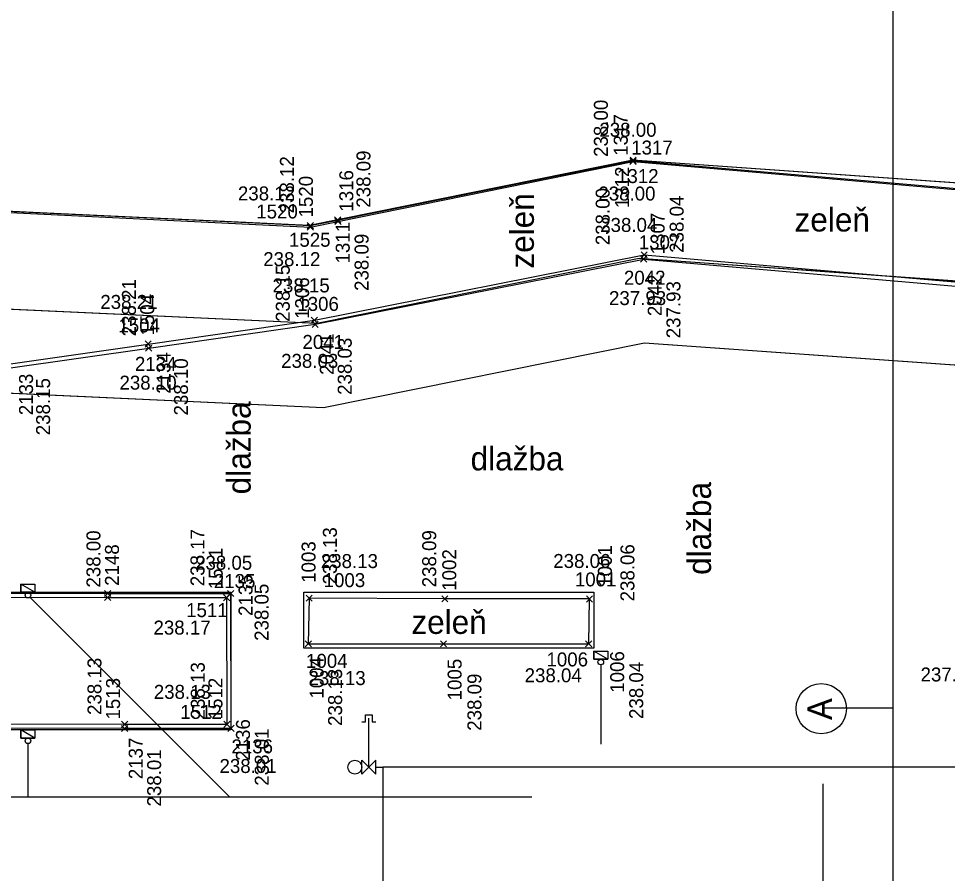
# Model space of a CAD drawing. Extents: x -264205 to -263659, y -1242401 to -1241986.
# Drawn here: x -263937.18 to -263903.94, y -1242086.44 to -1242055.86 of the extents above; entities that cross this region are included whole.
import ezdxf

# ---------------------------------------------------------------- set-up
doc = ezdxf.new("R2010")
doc.units = 0
for name, color, linetype in [('BOD_CISLO_2-2', 7, 'Continuous'), ('BOD_CISLO_2-3', 7, 'Continuous'), ('BOD_SYMBOL_2-2', 7, 'Continuous'), ('BOD_SYMBOL_2-3', 7, 'Continuous'), ('BOD_VYSKA_2-2', 7, 'Continuous'), ('BOD_VYSKA_2-3', 7, 'Continuous'), ('HESCON_OSI_STAVBY_KFA', 7, 'Continuous'), ('POPIS_2-2', 7, 'Continuous'), ('POPIS_2-3', 7, 'Continuous'), ('PROJEKT_OBRUBNIKY_KOMUNIKACIE', 7, 'Continuous'), ('RAM_NA_TLAC_2-3_1-250', 7, 'Continuous'), ('SITUACIA_DSP_2D', 7, 'Continuous'), ('SO_20-4_OBRUBNIKY_DOLNA_HRANA', 7, 'Continuous'), ('SO_20-4_OBRUBNIKY_HORNA_HRANA', 7, 'Continuous')]:
    doc.layers.add(name, color=color, linetype=linetype)

msp = doc.modelspace()

# ---------------------------------------------------------------- linework, layer by layer
at = {"layer": 'BOD_SYMBOL_2-2'}
for p, q in [((-263915.299, -1242061.082), (-263915.078, -1242060.86)), ((-263915.078, -1242061.082), (-263915.299, -1242060.86)), ((-263915.291, -1242061.039), (-263915.071, -1242060.818)), ((-263915.071, -1242061.039), (-263915.291, -1242060.818)), ((-263926.851, -1242063.374), (-263926.629, -1242063.154)), ((-263926.629, -1242063.374), (-263926.851, -1242063.154)), ((-263926.846, -1242063.43), (-263926.626, -1242063.208)), ((-263926.626, -1242063.43), (-263926.846, -1242063.208)), ((-263925.87, -1242063.177), (-263925.649, -1242062.955)), ((-263925.649, -1242063.177), (-263925.87, -1242062.955)), ((-263925.861, -1242063.222), (-263925.639, -1242063.002)), ((-263925.639, -1242063.222), (-263925.861, -1242063.002)), ((-263914.9, -1242064.418), (-263914.68, -1242064.198)), ((-263914.68, -1242064.418), (-263914.9, -1242064.198)), ((-263914.916, -1242064.569), (-263914.696, -1242064.349)), ((-263914.696, -1242064.569), (-263914.916, -1242064.349)), ((-263926.704, -1242066.758), (-263926.482, -1242066.536)), ((-263926.482, -1242066.758), (-263926.704, -1242066.536)), ((-263926.674, -1242066.904), (-263926.453, -1242066.683)), ((-263926.453, -1242066.904), (-263926.674, -1242066.683)), ((-263932.65, -1242067.613), (-263932.43, -1242067.391)), ((-263932.43, -1242067.613), (-263932.65, -1242067.391)), ((-263932.632, -1242067.759), (-263932.41, -1242067.539)), ((-263932.41, -1242067.759), (-263932.632, -1242067.539)), ((-263934.1, -1242076.534), (-263933.878, -1242076.312)), ((-263933.878, -1242076.534), (-263934.1, -1242076.312)), ((-263934.099, -1242076.681), (-263933.878, -1242076.461)), ((-263933.878, -1242076.681), (-263934.099, -1242076.461)), ((-263929.843, -1242076.684), (-263929.622, -1242076.463)), ((-263929.622, -1242076.684), (-263929.843, -1242076.463)), ((-263929.699, -1242076.538), (-263929.479, -1242076.316)), ((-263929.479, -1242076.538), (-263929.699, -1242076.316)), ((-263926.891, -1242076.701), (-263926.67, -1242076.481)), ((-263926.67, -1242076.701), (-263926.891, -1242076.481)), ((-263922.035, -1242076.725), (-263921.813, -1242076.505)), ((-263921.813, -1242076.725), (-263922.035, -1242076.505)), ((-263916.854, -1242076.731), (-263916.633, -1242076.511)), ((-263916.633, -1242076.731), (-263916.854, -1242076.511)), ((-263926.92, -1242078.335), (-263926.698, -1242078.113)), ((-263926.698, -1242078.335), (-263926.92, -1242078.113)), ((-263922.082, -1242078.333), (-263921.861, -1242078.113)), ((-263921.861, -1242078.333), (-263922.082, -1242078.113)), ((-263916.887, -1242078.338), (-263916.666, -1242078.117)), ((-263916.666, -1242078.338), (-263916.887, -1242078.117)), ((-263933.492, -1242081.218), (-263933.272, -1242080.997)), ((-263933.272, -1242081.218), (-263933.492, -1242080.997)), ((-263933.49, -1242081.366), (-263933.269, -1242081.144)), ((-263933.269, -1242081.366), (-263933.49, -1242081.144)), ((-263929.833, -1242081.218), (-263929.611, -1242080.998)), ((-263929.611, -1242081.218), (-263929.833, -1242080.998)), ((-263929.688, -1242081.363), (-263929.468, -1242081.141)), ((-263929.468, -1242081.363), (-263929.688, -1242081.141))]:
    msp.add_line(p, q, dxfattribs=at)
at = {"layer": 'BOD_SYMBOL_2-3'}
for p, q in [((-263915.078, -1242061.082), (-263915.299, -1242060.86)), ((-263915.078, -1242060.86), (-263915.299, -1242061.082)), ((-263915.071, -1242061.039), (-263915.291, -1242060.818)), ((-263915.071, -1242060.818), (-263915.291, -1242061.039)), ((-263926.629, -1242063.374), (-263926.851, -1242063.154)), ((-263926.629, -1242063.154), (-263926.851, -1242063.374)), ((-263926.626, -1242063.43), (-263926.846, -1242063.208)), ((-263926.626, -1242063.208), (-263926.846, -1242063.43)), ((-263925.649, -1242063.177), (-263925.87, -1242062.955)), ((-263925.649, -1242062.955), (-263925.87, -1242063.177)), ((-263925.639, -1242063.222), (-263925.861, -1242063.002)), ((-263925.639, -1242063.002), (-263925.861, -1242063.222)), ((-263914.68, -1242064.418), (-263914.9, -1242064.198)), ((-263914.68, -1242064.198), (-263914.9, -1242064.418)), ((-263914.696, -1242064.569), (-263914.916, -1242064.349)), ((-263914.696, -1242064.349), (-263914.916, -1242064.569)), ((-263926.482, -1242066.758), (-263926.704, -1242066.536)), ((-263926.482, -1242066.536), (-263926.704, -1242066.758)), ((-263926.453, -1242066.904), (-263926.674, -1242066.683)), ((-263926.453, -1242066.683), (-263926.674, -1242066.904)), ((-263932.43, -1242067.613), (-263932.65, -1242067.391)), ((-263932.43, -1242067.391), (-263932.65, -1242067.613)), ((-263932.41, -1242067.759), (-263932.632, -1242067.539)), ((-263932.41, -1242067.539), (-263932.632, -1242067.759)), ((-263933.878, -1242076.534), (-263934.1, -1242076.312)), ((-263933.878, -1242076.312), (-263934.1, -1242076.534)), ((-263933.878, -1242076.681), (-263934.099, -1242076.461)), ((-263933.878, -1242076.461), (-263934.099, -1242076.681)), ((-263929.622, -1242076.684), (-263929.843, -1242076.463)), ((-263929.622, -1242076.463), (-263929.843, -1242076.684)), ((-263929.479, -1242076.538), (-263929.699, -1242076.316)), ((-263929.479, -1242076.316), (-263929.699, -1242076.538)), ((-263926.67, -1242076.701), (-263926.891, -1242076.481)), ((-263926.67, -1242076.481), (-263926.891, -1242076.701)), ((-263921.813, -1242076.725), (-263922.035, -1242076.505)), ((-263921.813, -1242076.505), (-263922.035, -1242076.725)), ((-263916.633, -1242076.731), (-263916.854, -1242076.511)), ((-263916.633, -1242076.511), (-263916.854, -1242076.731)), ((-263926.698, -1242078.335), (-263926.92, -1242078.113)), ((-263926.698, -1242078.113), (-263926.92, -1242078.335)), ((-263921.861, -1242078.333), (-263922.082, -1242078.113)), ((-263921.861, -1242078.113), (-263922.082, -1242078.333)), ((-263916.666, -1242078.338), (-263916.887, -1242078.117)), ((-263916.666, -1242078.117), (-263916.887, -1242078.338)), ((-263933.272, -1242081.218), (-263933.492, -1242080.997)), ((-263933.272, -1242080.997), (-263933.492, -1242081.218)), ((-263933.269, -1242081.366), (-263933.49, -1242081.144)), ((-263933.269, -1242081.144), (-263933.49, -1242081.366)), ((-263929.611, -1242081.218), (-263929.833, -1242080.998)), ((-263929.611, -1242080.998), (-263929.833, -1242081.218)), ((-263929.468, -1242081.363), (-263929.688, -1242081.141)), ((-263929.468, -1242081.141), (-263929.688, -1242081.363))]:
    msp.add_line(p, q, dxfattribs=at)
at = {"layer": 'HESCON_OSI_STAVBY_KFA'}
for q in [(-263908.393, -1242083.237), (-263908.393, -1242246.707)]:
    msp.add_line((-263908.393, -1242083.237), q, dxfattribs=at)
msp.add_circle((-263908.453, -1242080.545), 0.899, dxfattribs=at)
at = {"layer": 'PROJEKT_OBRUBNIKY_KOMUNIKACIE'}
for p, q in [((-263915.197, -1242060.921), (-263926.771, -1242063.254)), ((-263895.455, -1242062.322), (-263915.197, -1242060.921)), ((-263926.771, -1242063.254), (-263950.745, -1242062.149)), ((-263953.617, -1242076.382), (-263929.58, -1242076.382)), ((-263929.58, -1242076.382), (-263929.58, -1242081.307)), ((-263926.968, -1242076.382), (-263921.968, -1242076.382)), ((-263926.968, -1242078.382), (-263926.968, -1242076.382)), ((-263921.968, -1242076.382), (-263916.593, -1242076.382)), ((-263916.593, -1242076.382), (-263916.593, -1242078.382)), ((-263921.968, -1242078.382), (-263926.968, -1242078.382)), ((-263916.593, -1242078.382), (-263921.968, -1242078.382)), ((-263929.58, -1242081.307), (-263953.617, -1242081.307))]:
    msp.add_line(p, q, dxfattribs=at)
for points in [[(-263863.949, -1242065.106), (-263895.455, -1242062.322), (-263915.197, -1242060.921), (-263926.771, -1242063.254), (-263950.745, -1242062.149), (-263959.468, -1242059.534)], [(-263864.257, -1242068.593), (-263895.733, -1242065.811), (-263914.971, -1242064.445), (-263926.501, -1242066.77), (-263951.337, -1242065.625), (-263959.611, -1242063.145)], [(-263864.521, -1242071.581), (-263895.971, -1242068.802), (-263914.777, -1242067.467), (-263926.271, -1242069.784), (-263951.845, -1242068.605), (-263959.611, -1242066.277)]]:
    msp.add_lwpolyline(points, dxfattribs=at)
at = {"layer": 'RAM_NA_TLAC_2-3_1-250'}
msp.add_line((-263908.389, -1242080.511), (-263905.889, -1242080.511), dxfattribs=at)
msp.add_lwpolyline([(-263980.139, -1242275.511), (-263980.139, -1241985.511), (-263905.889, -1241985.511), (-263905.889, -1242275.511)], close=True, dxfattribs=at)
at = {"layer": 'SITUACIA_DSP_2D'}
for p, q in [((-263915.197, -1242060.921), (-263926.771, -1242063.254)), ((-263915.197, -1242060.921), (-263926.771, -1242063.254)), ((-263895.455, -1242062.322), (-263915.197, -1242060.921)), ((-263895.455, -1242062.322), (-263915.197, -1242060.921)), ((-263926.771, -1242063.254), (-263950.745, -1242062.149)), ((-263926.771, -1242063.254), (-263950.745, -1242062.149)), ((-263914.971, -1242064.445), (-263926.501, -1242066.77)), ((-263895.733, -1242065.811), (-263914.971, -1242064.445)), ((-263926.501, -1242066.77), (-263951.337, -1242065.625)), ((-263914.777, -1242067.467), (-263926.271, -1242069.784)), ((-263895.971, -1242068.802), (-263914.777, -1242067.467)), ((-263926.271, -1242069.784), (-263951.845, -1242068.605)), ((-263937.093, -1242076.382), (-263937.093, -1242076.092)), ((-263937.093, -1242076.092), (-263936.593, -1242076.092)), ((-263936.593, -1242076.382), (-263937.093, -1242076.092)), ((-263936.593, -1242076.382), (-263937.093, -1242076.092)), ((-263937.093, -1242076.092), (-263937.093, -1242076.382)), ((-263936.593, -1242076.092), (-263936.593, -1242076.382)), ((-263953.617, -1242076.382), (-263929.58, -1242076.382)), ((-263936.593, -1242076.382), (-263937.093, -1242076.382)), ((-263937.093, -1242076.382), (-263936.593, -1242076.382)), ((-263936.772, -1242076.553), (-263929.628, -1242083.697)), ((-263929.58, -1242076.382), (-263929.58, -1242081.307)), ((-263926.968, -1242076.382), (-263921.968, -1242076.382)), ((-263926.968, -1242078.382), (-263926.968, -1242076.382)), ((-263926.968, -1242076.382), (-263926.968, -1242076.382)), ((-263921.968, -1242076.382), (-263916.593, -1242076.382)), ((-263916.593, -1242076.382), (-263916.593, -1242078.382)), ((-263921.968, -1242078.382), (-263926.968, -1242078.382)), ((-263916.593, -1242078.382), (-263921.968, -1242078.382)), ((-263916.593, -1242078.777), (-263916.593, -1242078.487)), ((-263916.593, -1242078.487), (-263916.093, -1242078.487)), ((-263916.093, -1242078.777), (-263916.593, -1242078.487)), ((-263916.093, -1242078.777), (-263916.593, -1242078.487)), ((-263916.593, -1242078.487), (-263916.593, -1242078.777)), ((-263916.093, -1242078.487), (-263916.093, -1242078.777)), ((-263916.093, -1242078.777), (-263916.593, -1242078.777)), ((-263916.593, -1242078.777), (-263916.093, -1242078.777)), ((-263916.343, -1242078.977), (-263916.343, -1242081.82)), ((-263924.768, -1242081.015), (-263924.768, -1242080.765)), ((-263924.768, -1242080.765), (-263924.518, -1242080.765)), ((-263924.518, -1242080.765), (-263924.518, -1242081.015)), ((-263924.893, -1242081.015), (-263924.768, -1242081.015)), ((-263924.643, -1242082.64), (-263924.643, -1242080.89)), ((-263924.518, -1242081.015), (-263924.393, -1242081.015)), ((-263929.58, -1242081.307), (-263953.617, -1242081.307)), ((-263937.093, -1242081.597), (-263937.093, -1242081.307)), ((-263937.093, -1242081.307), (-263936.593, -1242081.307)), ((-263936.593, -1242081.597), (-263937.093, -1242081.307)), ((-263936.593, -1242081.597), (-263937.093, -1242081.307)), ((-263937.093, -1242081.307), (-263937.093, -1242081.597)), ((-263936.593, -1242081.307), (-263936.593, -1242081.597)), ((-263936.593, -1242081.597), (-263937.093, -1242081.597)), ((-263937.093, -1242081.597), (-263936.593, -1242081.597)), ((-263936.843, -1242081.797), (-263936.843, -1242083.697)), ((-263924.393, -1242082.39), (-263924.893, -1242082.89)), ((-263924.893, -1242082.89), (-263924.893, -1242082.39)), ((-263924.893, -1242082.39), (-263924.393, -1242082.89)), ((-263924.393, -1242082.89), (-263924.393, -1242082.39)), ((-263924.393, -1242082.64), (-263924.143, -1242082.64)), ((-263788.143, -1242082.64), (-263924.143, -1242082.64)), ((-263924.143, -1242082.64), (-263924.143, -1242185.14)), ((-263951.618, -1242083.697), (-263918.806, -1242083.697))]:
    msp.add_line(p, q, dxfattribs=at)
for centre, radius in [((-263936.843, -1242076.482), 0.1), ((-263916.343, -1242078.877), 0.1), ((-263936.843, -1242081.697), 0.1), ((-263925.143, -1242082.64), 0.25)]:
    msp.add_circle(centre, radius, dxfattribs=at)
at = {"layer": 'SO_20-4_OBRUBNIKY_DOLNA_HRANA'}
for points in [[(-263959.478, -1242063.189), (-263952.785, -1242065.784), (-263948.11, -1242067.593), (-263944.393, -1242069.033), (-263943.407, -1242069.198), (-263943.371, -1242069.195), (-263937.472, -1242068.355), (-263932.521, -1242067.649), (-263926.563, -1242066.793)], [(-263926.563, -1242066.793), (-263914.806, -1242064.459), (-263888.634, -1242066.727), (-263862.406, -1242069), (-263841.103, -1242070.841)], [(-263953.462, -1242070.261), (-263953.509, -1242076.368), (-263947.48, -1242076.383), (-263939.492, -1242076.412), (-263933.989, -1242076.423), (-263929.589, -1242076.427)], [(-263929.589, -1242076.427), (-263929.578, -1242081.252), (-263933.379, -1242081.255), (-263938.374, -1242081.247), (-263943.352, -1242081.243), (-263948.361, -1242081.234), (-263953.912, -1242081.238), (-263959.581, -1242081.233)]]:
    msp.add_lwpolyline(points, dxfattribs=at)
at = {"layer": 'SO_20-4_OBRUBNIKY_HORNA_HRANA'}
for points in [[(-263925.759, -1242063.066), (-263915.181, -1242060.928), (-263888.287, -1242063.258), (-263862.248, -1242065.492), (-263835.778, -1242067.791)], [(-263925.75, -1242063.112), (-263915.188, -1242060.971), (-263888.294, -1242063.301), (-263862.255, -1242065.535), (-263835.78, -1242067.841)], [(-263943.105, -1242062.468), (-263926.74, -1242063.264), (-263925.759, -1242063.066)], [(-263943.105, -1242062.523), (-263926.736, -1242063.319), (-263925.75, -1242063.112)], [(-263959.477, -1242063.034), (-263952.729, -1242065.645), (-263948.057, -1242067.457), (-263944.366, -1242068.887), (-263943.41, -1242069.05), (-263937.471, -1242068.206), (-263932.54, -1242067.502), (-263926.593, -1242066.647)], [(-263926.593, -1242066.647), (-263914.79, -1242064.308), (-263888.584, -1242066.589), (-263862.408, -1242068.845), (-263841.091, -1242070.689)], [(-263959.518, -1242070.377), (-263953.609, -1242070.41), (-263953.653, -1242076.515), (-263947.479, -1242076.534), (-263939.482, -1242076.558), (-263933.988, -1242076.571), (-263929.732, -1242076.573), (-263929.722, -1242081.108), (-263933.382, -1242081.107), (-263938.392, -1242081.1), (-263943.361, -1242081.098), (-263948.363, -1242081.089), (-263953.88, -1242081.091), (-263959.58, -1242081.083)], [(-263916.743, -1242076.621), (-263921.924, -1242076.615), (-263926.78, -1242076.591), (-263926.809, -1242078.224), (-263921.971, -1242078.223), (-263916.776, -1242078.227), (-263916.743, -1242076.621)]]:
    msp.add_lwpolyline(points, dxfattribs=at)

# ---------------------------------------------------------------- texts
at = {"layer": 'BOD_CISLO_2-2'}
for s, p in [('1317', (-263915.254, -1242060.72)), ('1312', (-263915.761, -1242061.741)), ('1520', (-263928.672, -1242063.008)), ('1525', (-263927.501, -1242064.02)), ('1307', (-263914.983, -1242064.11)), ('2042', (-263915.514, -1242065.377)), ('1306', (-263927.203, -1242066.314)), ('1504', (-263933.606, -1242067.083)), ('2041', (-263927.019, -1242067.675)), ('2134', (-263933.013, -1242068.459)), ('2135', (-263930.19, -1242076.231)), ('1003', (-263926.261, -1242076.197)), ('1001', (-263917.269, -1242076.17)), ('1511', (-263931.181, -1242077.27)), ('1006', (-263918.286, -1242079.034)), ('1004', (-263926.891, -1242079.085)), ('1512', (-263931.389, -1242080.911)), ('2136', (-263929.56, -1242082.144))]:
    msp.add_text(s, height=0.5, dxfattribs=at).set_placement(p)
at = {"layer": 'BOD_CISLO_2-3'}
for s, p in [('1317', (-263915.378, -1242060.764)), ('1312', (-263915.332, -1242062.638)), ('1520', (-263926.646, -1242062.972)), ('1316', (-263925.199, -1242062.764)), ('1307', (-263914.057, -1242064.29)), ('1311', (-263925.328, -1242064.617)), ('1306', (-263926.781, -1242066.6)), ('2042', (-263914.163, -1242066.5)), ('1504', (-263932.326, -1242067.195)), ('2041', (-263925.896, -1242068.605)), ('2134', (-263931.74, -1242069.279)), ('2133', (-263936.661, -1242070.047)), ('2148', (-263933.585, -1242076.152)), ('1511', (-263929.874, -1242076.272)), ('1003', (-263926.551, -1242076.044)), ('1002', (-263921.514, -1242076.328)), ('1001', (-263915.946, -1242076.184)), ('2135', (-263928.805, -1242077.229)), ('1006', (-263915.506, -1242079.976)), ('1004', (-263926.26, -1242080.185)), ('1005', (-263921.323, -1242080.248)), ('1513', (-263933.547, -1242080.934)), ('1512', (-263929.882, -1242080.927)), ('2136', (-263928.898, -1242082.409)), ('2137', (-263932.736, -1242083.068))]:
    msp.add_text(s, height=0.5, rotation=90, dxfattribs=at).set_placement(p)
at = {"layer": 'BOD_VYSKA_2-2'}
for s, p in [('238.00', (-263916.392, -1242060.084)), ('238.12', (-263929.328, -1242062.362)), ('238.00', (-263916.43, -1242062.366)), ('238.04', (-263916.364, -1242063.49)), ('238.12', (-263928.422, -1242064.713)), ('238.15', (-263928.088, -1242065.653)), ('238.21', (-263934.253, -1242066.244)), ('237.93', (-263916.048, -1242066.106)), ('238.03', (-263927.781, -1242068.352)), ('238.10', (-263933.567, -1242069.132)), ('238.05', (-263930.862, -1242075.575)), ('238.13', (-263926.361, -1242075.515)), ('238.06', (-263918.043, -1242075.512)), ('238.17', (-263932.35, -1242077.895)), ('238.13', (-263926.8, -1242079.701)), ('238.04', (-263919.068, -1242079.602)), ('237.88', (-263904.898, -1242079.573)), ('238.13', (-263932.338, -1242080.194)), ('238.01', (-263929.987, -1242082.847))]:
    msp.add_text(s, height=0.5, dxfattribs=at).set_placement(p)
at = {"layer": 'BOD_VYSKA_2-3'}
for s, p in [('238.00', (-263916.089, -1242060.805)), ('238.12', (-263927.323, -1242062.825)), ('238.09', (-263924.585, -1242062.622)), ('238.00', (-263916.025, -1242063.964)), ('238.04', (-263913.377, -1242064.235)), ('238.09', (-263924.652, -1242065.599)), ('238.15', (-263927.473, -1242066.707)), ('238.21', (-263932.978, -1242067.224)), ('237.93', (-263913.493, -1242067.294)), ('238.03', (-263925.256, -1242069.318)), ('238.10', (-263931.115, -1242070.056)), ('238.15', (-263936.05, -1242070.764)), ('238.00', (-263934.249, -1242076.213)), ('238.17', (-263930.525, -1242076.165)), ('238.13', (-263925.787, -1242076.1)), ('238.09', (-263922.232, -1242076.204)), ('238.06', (-263915.139, -1242076.707)), ('238.05', (-263928.231, -1242078.119)), ('238.13', (-263934.211, -1242080.77)), ('238.04', (-263914.825, -1242080.915)), ('238.13', (-263930.515, -1242080.926)), ('238.13', (-263925.6, -1242081.163)), ('238.09', (-263920.615, -1242081.336)), ('238.01', (-263928.224, -1242083.301)), ('238.01', (-263932.076, -1242084.045))]:
    msp.add_text(s, height=0.5, rotation=90, dxfattribs=at).set_placement(p)
at = {"layer": 'HESCON_OSI_STAVBY_KFA'}
msp.add_text('A', height=0.875, rotation=90, dxfattribs=at).set_placement((-263908.072, -1242080.952))
at = {"layer": 'POPIS_2-2'}
for s, p in [('zeleň', (-263909.408, -1242063.474)), ('dlažba', (-263921.002, -1242072.02)), ('zeleň', (-263923.121, -1242077.871))]:
    msp.add_text(s, height=0.8438, dxfattribs=at).set_placement(p)
at = {"layer": 'POPIS_2-3'}
for s, p in [('zeleň', (-263918.737, -1242064.802)), ('dlažba', (-263928.872, -1242072.878)), ('dlažba', (-263912.396, -1242075.759))]:
    msp.add_text(s, height=0.8438, rotation=90, dxfattribs=at).set_placement(p)

doc.saveas('drawing.dxf')
